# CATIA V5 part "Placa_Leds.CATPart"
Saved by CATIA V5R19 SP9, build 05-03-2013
Part number: Placa_Leds
Bounding box of the stored display mesh (mm): x 0 to 44, y 0 to 44, z 0 to 2
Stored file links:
  D:\PROGRAMACION\PROYECTOS\DEFCON\CAD\Placa_Leds.CATPart
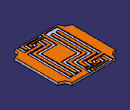
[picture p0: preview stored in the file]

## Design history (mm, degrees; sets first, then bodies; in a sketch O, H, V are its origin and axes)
Body1 (main body)
  Sketch1 on xy-plane, origin (0, 0, 0), H (1, 0, 0), V (0, 1, 0)
    line L1 (5.25, 0) -> (38.75, 0)
    line L2 (44, 5.25) -> (44, 38.75)
    line L3 (38.75, 44) -> (5.25, 44)
    line L4 (0, 38.75) -> (0, 5.25)
    point P1 (44, 0)
    point P2 (44, 44)
    point P3 (0, 44)
    arc A1 centre (0, 44) radius 5.25 from (0, 38.75) to (5.25, 44) ccw
    arc A2 centre (44, 44) radius 5.25 from (38.75, 44) to (44, 38.75) ccw
    arc A3 centre (0, 0) radius 5.25 from (5.25, 0) to (0, 5.25) ccw
    arc A4 centre (44, 0) radius 5.25 from (44, 5.25) to (38.75, 0) ccw
    radius A3 = 5.25
    radius A1 = 5.25
    radius A2 = 5.25
    radius A4 = 5.25
    distance P2 P3 = 44 {= Sketch1.distance(L4 L2)}
    distance P1 P2 = 44
    distance L3 L1 = 44 {= Sketch1.distance(P1 P2)}
    distance L4 L2 = 44
    horizontal: L1 H, L3 H
    vertical: L2 V, L4 V
    coincidence: H L1, L4 V, P3 L3, P2 L3, P3 L4, P1 L2
  Pad1: profile Sketch1, direction (0, 0, 1), length 1.5
  Body2
    Sketch2 on end face of Pad1, origin (0, 0, 1.5), H (1, 0, 0), V (0, 1, 0)
      construction line L1 (22, 51) -> (22, -7)
      reference projected line E1 (0, 40) -> (0, 0) from edge [start face of Pad1 | face of Pad1 from Sketch1.L4]
      reference projected line E2 (44, 0) -> (44, 40) from edge [start face of Pad1 | face of Pad1 from Sketch1.L2]
      line L2 (9, 38) -> (11, 38)
      point P4 (11, 38)
      line L3 (11, 38) -> (11, 42)
      line L4 (11, 42) -> (23, 42)
      line L5 (23, 42) -> (23, 44)
      line L6 (23, 44) -> (21, 44)
      line L7 (21, 44) -> (21, 43)
      line L8 (21, 43) -> (9, 43)
      line L9 (9, 43) -> (9, 38)
      line L10 (7, 43.1037) -> (7, 38)
      point P12 (7, 38)
      line L11 (5.25, 44) -> (7, 44)
      line L12 (13, 38) -> (13, 41)
      line L13 (13, 41) -> (25, 41)
      line L14 (25, 41) -> (25, 44)
      line L15 (23.1378, 40) -> (15, 40)
      line L16 (15, 40) -> (15, 38)
      line L17 (15, 38) -> (13, 38)
      point P20 (25, 38)
      line L18 (25, 38) -> (25, 40)
      point P21 (25, 40)
      line L19 (25, 40) -> (23.1378, 40)
      point P22 (27, 38)
      line L20 (9, 4) -> (11, 4)
      line L21 (11, 4) -> (11, 32)
      line L22 (11, 32) -> (23, 32)
      line L23 (23, 32) -> (23, 39)
      line L24 (23, 39) -> (21, 39)
      point P29 (21, 39)
      line L25 (21, 39) -> (21, 34)
      line L26 (21, 34) -> (9, 34)
      line L27 (9, 34) -> (9, 4)
      point P32 (21, 4)
      line L28 (21, 4) -> (23, 4)
      line L29 (23, 4) -> (23, 9)
      line L30 (23, 9) -> (35, 9)
      line L31 (35, 9) -> (35, 39)
      line L32 (35, 39) -> (33, 39)
      line L33 (33, 39) -> (33, 11)
      line L34 (33, 11) -> (21, 11)
      line L35 (21, 11) -> (21, 4)
      line L36 (21, 0) -> (21, 1)
      line L37 (21, 1) -> (33, 1)
      line L38 (33, 1) -> (33, 5)
      line L39 (33, 5) -> (35, 5)
      line L40 (35, 5) -> (35, 0)
      line L41 (35, 0) -> (23, 0)
      line L42 (23, 0) -> (23, 0)
      line L43 (23, 0) -> (21, 0)
      reference projected line E3 (40, 44) -> (0, 44) from edge [start face of Pad1 | face of Pad1 from Sketch1.L3]
      reference projected line E4 (40, 44) -> (0, 44) from edge [start face of Pad1 | face of Pad1 from Sketch1.L3]
      line L44 (25, 44) -> (27, 44)
      reference projected line E5 (40, 44) -> (0, 44) from edge [start face of Pad1 | face of Pad1 from Sketch1.L3]
      reference projected line E6 (3, 5) -> (13, 5) from Sketch5.L10
      construction line L45 (10, 52) -> (10, -20)
      reference projected line E7 (5, 34) -> (5, 5) from Sketch5.L4
      reference projected line E8 (15, 5) -> (15, 34) from Sketch5.L5
      reference projected line E9 (13, 38) -> (3, 38) from Sketch5.L1
      axis line L46 (34, 40.7422) -> (34, -9.2578)
      reference projected line E10 (29, 34) -> (29, 5) from Sketch5.L8
      reference projected line E11 (39, 5) -> (39, 34) from Sketch5.L2
      reference projected line E12 (27, 5) -> (37, 5) from Sketch5.L3
      reference projected line E13 (0, 0) -> (40, 0) from edge [start face of Pad1 | face of Pad1 from Sketch1.L1]
      reference projected line E14 (25, 38) -> (15, 38) from Sketch5.L9
      line L47 (19, 35) -> (19, 39)
      point P53 (19, 39)
      line L48 (19, 39) -> (17, 39)
      line L49 (17, 39) -> (17, 37)
      line L50 (17, 37) -> (7, 37)
      point P56 (7, 37)
      line L51 (7, 37) -> (7, 38)
      reference projected line E15 (17, 33) -> (17, 6) from Sketch5.L6
      reference projected line E16 (13, 38) -> (3, 38) from Sketch5.L1
      line L52 (37, 32.4794) -> (37, 40)
      point P58 (37, 40)
      line L53 (37, 40) -> (27, 40)
      line L54 (27, 40) -> (27, 38)
      reference projected line E17 (37, 38) -> (27, 38) from Sketch5.L11
      line L55 (27, 44) -> (38.75, 44)
      line L56 (44, 38.75) -> (44, 5.25)
      line L57 (38.75, 0) -> (37, 0)
      line L58 (37, 1) -> (37, 6)
      reference projected line E18 (44, 0) -> (44, 40) from edge [start face of Pad1 | face of Pad1 from Sketch1.L2]
      reference projected line E19 (27, 5) -> (37, 5) from Sketch5.L3
      line L59 (19, 35) -> (7, 35)
      point P61 (7, 35)
      line L60 (7, 35) -> (7, 1)
      point P62 (7, 1)
      line L61 (7, 1) -> (17, 1)
      line L62 (17, 1) -> (17, 26)
      line L63 (17, 26) -> (29, 26)
      line L64 (29, 26) -> (29, 39)
      point P66 (29, 39)
      line L65 (29, 39) -> (31, 39)
      line L66 (31, 39) -> (31, 13)
      line L67 (31, 13) -> (19, 13)
      line L68 (19, 13) -> (19, 3)
      line L69 (19, 0) -> (5.25, 0)
      line L70 (0, 5.25) -> (0, 38.75)
      line L71 (25, 38) -> (25, 30)
      line L72 (25, 30) -> (13, 30)
      point P72 (13, 30)
      line L73 (13, 30) -> (13, 4)
      line L74 (13, 4) -> (15, 4)
      point P74 (15, 4)
      line L75 (15, 4) -> (15, 28)
      line L76 (15, 28) -> (27, 28)
      point P76 (27, 28)
      line L77 (27, 28) -> (27, 38)
      line L78 (37, 6) -> (27, 6)
      point P78 (27, 6)
      line L79 (27, 6) -> (27, 4)
      point P79 (27, 4)
      line L80 (27, 4) -> (25, 4)
      line L81 (25, 4) -> (25, 8)
      line L82 (25, 8) -> (37, 8)
      line L83 (37, 8) -> (37, 32.4794)
      reference projected line E20 (27, 6) -> (27, 33) from Sketch5.L7
      line L84 (7, 43.1037) -> (7, 44)
      reference projected line E21 (15, 5) -> (15, 38) from Sketch5.L5
      line L85 (37, 1) -> (37, 0)
      reference projected line E22 (0, 0) -> (44, 0) from edge [start face of Pad1 | face of Pad1 from Sketch1.L1]
      line L86 (19, 3) -> (29, 3)
      line L87 (29, 3) -> (29, 5)
      line L88 (29, 5) -> (31, 5)
      line L89 (31, 5) -> (31, 2)
      line L90 (31, 2) -> (19, 2)
      point P90 (19, 2)
      line L91 (19, 2) -> (19, 0)
      reference projected line E23 (29, 38) -> (29, 5) from Sketch5.L8
      reference projected line E24 (29, 5) -> (39, 5) from Sketch5.L3
      projected arc E25 centre (0, 44) radius 5.25 from (0, 38.75) to (5.25, 44) ccw from edge [start face of Pad1 | face of Pad1 from Sketch1.A1]
      projected arc E26 centre (44, 44) radius 5.25 from (38.75, 44) to (44, 38.75) ccw from edge [start face of Pad1 | face of Pad1 from Sketch1.A2]
      projected arc E27 centre (0, 0) radius 5.25 from (5.25, 0) to (0, 5.25) ccw from edge [start face of Pad1 | face of Pad1 from Sketch1.A3]
      projected arc E28 centre (44, 0) radius 5.25 from (44, 5.25) to (38.75, 0) ccw from edge [start face of Pad1 | face of Pad1 from Sketch1.A4]
      distance L10 L9 = 2
      distance L3 L12 = 2
      distance L16 L12 = 2
      distance L15 L13 = 1
      distance L4 L8 = 1
      distance L3 L9 = 2
      length L6 = 2
      length L44 = 2
      distance L5 L14 = 2
      length L20 = 2
      distance L22 L26 = 2
      distance L20 E6 = 1
      distance L25 L23 = 2
      distance L26 E9 = 4
      distance L34 L30 = 2
      distance L33 L31 = 2
      distance L38 L40 = 2
      length L43 = 2
      distance L37 L41 = 1
      distance L4 L13 = 1
      distance L24 E14 = 1
      distance L50 L2 = 1
      distance L32 E17 = 1
      distance L58 L31 = 2
      distance E19 L30 = 4
      distance L59 L50 = 2
      distance L64 L66 = 2
      distance L66 L33 = 2
      distance L62 L66 = 14
      distance L67 L34 = 2
      distance L81 L79 = 2
      distance L82 L78 = 2
      distance L82 L30 = 1
      distance L72 L22 = 2
      distance L76 L72 = 2
      distance L63 L76 = 2
      distance L15 L48 = 1
      length L48 = 2
      distance L62 L68 = 2
      distance L86 L28 = 1
      distance L87 L89 = 2
      distance L90 L86 = 1
      vertical: L1 V, L3 V, L5 V, L7 V, L9 V, L10 V, L12 V, L14 V, L16 V, L18 V, L21 V, L23 V, L25 V, L27 V, L29 V, L31 V, L33 V, L35 V, L36 V, L38 V, L40 V, L42 V, L45 V, L46 V, L47 V, L49 V, L51 V, L52 V, L54 V, L56 V, L58 V, L60 V, L62 V, L64 V, L66 V, L68 V, L70 V, L71 V, L73 V, L75 V, L77 V, L79 V, L81 V, L83 V, L84 V, L85 V, L87 V, L89 V, L91 V
      symmetry: E1 E2 L1, L7 L5 L1, L35 L29 L1, E7 E8 L45, L27 L21 L45, E10 E11 L46, L33 L31 L46, L38 L40 L46, L36 L42 L1
      horizontal: L2 H, L4 H, L6 H, L8 H, L11 H, L13 H, L15 H, L17 H, L19 H, L20 H, L22 H, L24 H, L26 H, L28 H, L30 H, L32 H, L34 H, L37 H, L39 H, L41 H, L43 H, L44 H, L48 H, L50 H, L53 H, L55 H, L57 H, L59 H, L61 H, L63 H, L65 H, L67 H, L69 H, L72 H, L74 H, L76 H, L78 H, L80 H, L82 H, L86 H, L88 H, L90 H
      coincidence: P20 L2, P21 L15, P22 L2, P29 L7, P32 L7, L6 E3, L11 E4, L2 P12, L17 P4, L44 E5, L18 L14, L28 L20, E12 L39, E13 L43, P53 L24, P56 L10, L49 E15, E16 L2, P58 L15, L56 E18, P61 L10, P62 L37, P66 L32, P72 L12, P74 L16, P76 L54, L20 L74, P78 L77, P79 L20, L58 L83, L79 E20, L16 E21, L41 E22, P90 L68, L68 L91, L87 E23, L88 E24
    Pad2: profile Sketch2, direction (0, 0, 1), length 0.5
    Sketch3 "LEDS" on end face of Pad1, origin (0, 0, 1.5), H (1, 0, 0), V (0, 1, 0)
      line L1 (5, 38) -> (15, 38)
      line L2 (39, 38) -> (39, 5)
      line L3 (39, 5) -> (29, 5)
      line L4 (5, 5) -> (5, 38)
      line L5 (15, 38) -> (15, 5)
      point P6 (15, 5)
      line L6 (17, 38) -> (17, 5)
      point P7 (17, 38)
      line L7 (27, 38) -> (27, 5)
      point P9 (27, 38)
      point P10 (27, 5)
      line L8 (29, 38) -> (29, 5)
      point P11 (29, 38)
      line L9 (17, 38) -> (27, 38)
      line L10 (15, 5) -> (5, 5)
      line L11 (29, 38) -> (39, 38)
      line L12 (27, 5) -> (17, 5)
      reference projected line E1 (40, 44) -> (0, 44) from edge [start face of Pad1 | face of Pad1 from Sketch1.L3]
      reference projected line E2 (0, 0) -> (40, 0) from edge [start face of Pad1 | face of Pad1 from Sketch1.L1]
      axis line L13 (22, 50) -> (22, -10)
      reference projected line E3 (0, 40) -> (0, 0) from edge [start face of Pad1 | face of Pad1 from Sketch1.L4]
      reference projected line E4 (44, 0) -> (44, 40) from edge [start face of Pad1 | face of Pad1 from Sketch1.L2]
      length L2 = 33
      distance L11 E1 = 6
      distance L3 E2 = 5 (reference)
      length L10 = 10
      length L12 = 10 {= Sketch3.length(L10)}
      length L3 = 10 {= Sketch3.length(L10)}
      distance L5 L6 = 2
      distance L7 L8 = 2 {= Sketch3.distance(L5 L6)}
      horizontal: L1 H, L3 H, L9 H, L10 H, L11 H, L12 H
      vertical: L2 V, L4 V, L5 V, L6 V, L7 V, L8 V, L13 V
      coincidence: P6 L3, P7 L1, P9 L1, P10 L3, P11 L1, L1 L9, L3 L10, L9 L11, L3 L12
      symmetry: E3 E4 L13, L4 L2 L13
  Add1: tool Body2
  Body3
    Sketch4 "LEDS", origin (0, 0, 1.5), H (1, 0, 0), V (0, 1, 0), geometry linked from another document
    Pad3: profile Sketch4, direction (0, 0, 1), length 1, opposite side length -0.5, deactivated
  Add2: tool Body3, deactivated
  Sketch5 "LEDS" on end face of Pad1, origin (0, 0, 1.5), H (1, 0, 0), V (0, 1, 0)
    line L1 (5, 38) -> (15, 38)
    line L2 (39, 38) -> (39, 5)
    line L3 (39, 5) -> (29, 5)
    line L4 (5, 5) -> (5, 38)
    line L5 (15, 38) -> (15, 5)
    point P6 (15, 5)
    line L6 (17, 38) -> (17, 5)
    point P7 (17, 38)
    line L7 (27, 38) -> (27, 5)
    point P9 (27, 38)
    point P10 (27, 5)
    line L8 (29, 38) -> (29, 5)
    point P11 (29, 38)
    line L9 (17, 38) -> (27, 38)
    line L10 (15, 5) -> (5, 5)
    line L11 (29, 38) -> (39, 38)
    line L12 (27, 5) -> (17, 5)
    reference projected line E1 (40, 44) -> (0, 44) from edge [start face of Pad1 | face of Pad1 from Sketch1.L3]
    reference projected line E2 (0, 0) -> (40, 0) from edge [start face of Pad1 | face of Pad1 from Sketch1.L1]
    axis line L13 (22, 50) -> (22, -10)
    reference projected line E3 (0, 40) -> (0, 0) from edge [start face of Pad1 | face of Pad1 from Sketch1.L4]
    reference projected line E4 (44, 0) -> (44, 40) from edge [start face of Pad1 | face of Pad1 from Sketch1.L2]
    length L2 = 33
    distance L11 E1 = 6
    distance L3 E2 = 5 (reference)
    length L10 = 10
    length L12 = 10 {= Sketch5.length(L10)}
    length L3 = 10 {= Sketch5.length(L10)}
    distance L5 L6 = 2
    distance L7 L8 = 2 {= Sketch5.distance(L5 L6)}
    horizontal: L1 H, L3 H, L9 H, L10 H, L11 H, L12 H
    vertical: L2 V, L4 V, L5 V, L6 V, L7 V, L8 V, L13 V
    coincidence: P6 L3, P7 L1, P9 L1, P10 L3, P11 L1, L1 L9, L3 L10, L9 L11, L3 L12
    symmetry: E3 E4 L13, L4 L2 L13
